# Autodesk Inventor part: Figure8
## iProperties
Shininess: 77.0
Length Units: 11269
Angle Units: 11279
Time Units: 11290
Mass Units: 11283
Length Display Precision: 3
Angle Display Precision: 2
Compacted: True
Created: 2002-01
Part Number: Figure8
Document SubType Name: Modeling
Designer: ***
Density: 1 g/cm^3
Density: 0.0
Volumn: 0.0
Area: 0.0
PropertySet Name: Model Information
Control State: 0
Master: False
Checked Out: False
Author: ***
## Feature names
1. Extrusion1
